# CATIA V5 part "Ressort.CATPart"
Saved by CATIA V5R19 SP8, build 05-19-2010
Part number: Ressort
Bounding box of the stored display mesh (mm): x -13.714 to 11.192, y 18.676 to 62.081, z -4.993 to 4.995
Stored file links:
  G:\EU_thinkMotion\CFAO_2010\MMS_groupe3\MMS_groupe3\A reprendre\lpastor\lpastor\Ressort.CATPart
  C:\Users\Loïc\Documents\IFMA\Cours 2A\CFAO\Thinkmotion\Fourche avant.CATProduct
  G:\EU_thinkMotion\CFAO_2010\MMS_groupe3\MMS_groupe3\A reprendre\lpastor\lpastor\Piece piston bas.CATPart
  G:\EU_thinkMotion\CFAO_2010\MMS_groupe3\MMS_groupe3\A reprendre\lpastor\lpastor\Piece piston haut.CATPart
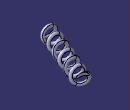
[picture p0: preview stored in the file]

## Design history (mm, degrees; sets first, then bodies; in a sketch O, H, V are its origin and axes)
Set1
  Line1: type PtPt, FirstPoint Point1, SecondPoint Point2
  Plane1: type Normal, Curve Line1
  Sketch1 on Plane1, origin (-9.9517, -23.3999, 0), H (-0.9202, 0.3914, 0), V (0, 0, 1)
    point P1 (18.1642, 3.5663)
    reference projected point E1 (16.3527, 0) from Line1
    distance P1 E1 = 4
  Helix1: Direction Line1, RefPoint Sketch1, Pitch 7, Height 150, TaperAngle 0
  Plane2: type Normal, Curve Helix1, RefPoint Sketch1
  Sketch2 on Plane2, origin (-18.6845, 1.862, -9.1039), H (0.0992, 0.9951, 0), V (-0.4341, 0.0433, 0.8998)
    circle A1 centre (-18.8551, 14.0809) radius 1
    point P1 (-18.8551, 14.0809)
    reference projected point E1 (-18.8551, 14.0809) from Sketch1
    radius A1 = 1
    coincidence: P1 E1
  Sweep1: type Unspec, Profile Sketch2, Guide Helix1
Set2
  Point1 "G": linked copy from another document
  Point2 "H": linked copy from another document
  DatumCurve1: linked copy from another document
  DatumSurface1: linked copy from another document
  DatumCurve2: linked copy from another document
Body1 (main body)
  CloseSurface1: CloseElement Sweep1
  Sketch3 on xy-plane, origin (0, 0, 0), H (1, 0, 0), V (0, 1, 0)
    point P1 (54.0981, 41.2294)
    line L1 (54.0981, 41.2294) -> (54.0981, 41.2294)
    point P2 (54.0981, 41.2294)
    line L2 (54.0981, 41.2294) -> (36.4867, -0.1812)
    line L3 (36.4867, -0.1812) -> (-55.5368, 38.9553)
    line L4 (-55.5368, 38.9553) -> (-37.9254, 80.3659)
    point P5 (-37.9254, 80.3659)
    line L5 (-37.9254, 80.3659) -> (54.0981, 41.2294)
    reference projected line E1 (-14.1262, 21.3439) -> (-4.9239, 17.4302) from edge of DatumCurve1
    reference projected line E2 (-14.1262, 21.3439) -> (-4.9239, 17.4302) from edge of DatumCurve1
    reference intersected line E3 (12.6875, 58.8408) -> (3.4852, 62.7545) from face of DatumSurface1
    reference intersected line E4 (12.6875, 58.8408) -> (3.4852, 62.7545) from face of DatumSurface1
    reference projected line E5 through (-15.0483, 6.3999) direction (0.3914, 0.9202) from edge of DatumCurve2
    reference projected line E6 through (-15.0483, 6.3999) direction (0.3914, 0.9202) from DatumCurve2
    distance L2 E5 = 50
    distance E6 L4 = 50
    parallelism: L3 L1, L4 L2, L5 L1, E1 L3, L5 E3
    coincidence: P5 L1, E2 L3, P1 P2, L5 E4
    perpendicularity: L4 L3
  Pocket1: profile Sketch3, direction (0, 0, -1), through (limit type 3), opposite side through (limit type 3), outer side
